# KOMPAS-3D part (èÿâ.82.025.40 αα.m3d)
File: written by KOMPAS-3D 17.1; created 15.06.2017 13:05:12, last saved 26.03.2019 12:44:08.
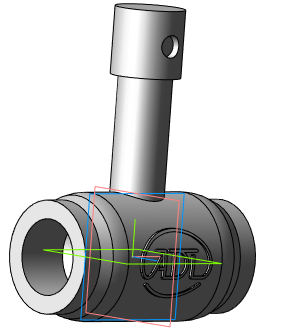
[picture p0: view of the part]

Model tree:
1. Операция без истории:2  (labels: Сталь 20  ГОСТ 1050-88)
